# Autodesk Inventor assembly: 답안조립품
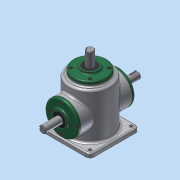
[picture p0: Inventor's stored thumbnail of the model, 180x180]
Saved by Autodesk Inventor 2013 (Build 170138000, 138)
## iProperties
Created: 2015-10
Part Number: 답안조립품
Document SubType Name: Assembly
Designer: dgall
Author: dgall
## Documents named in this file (14)
- C:\Users\dgall\Desktop\451007V1026\답안조립품.iam
- C:\Users\dgall\Desktop\451007V1026\본체.ipt
- C:\Users\dgall\Desktop\451007V1026\커버.ipt
- C:\Users\dgall\Desktop\451007V1026\베어링 6203.ipt
- C:\Users\dgall\Desktop\451007V1026\오일실.ipt
- C:\Users\dgall\Desktop\451007V1026\메인 축.ipt
- 메인 축.ipt
- C:\Users\dgall\Desktop\451007V1026\키 5x5.ipt
- C:\Users\dgall\Desktop\451007V1026\메인 베벨기어.ipt
- C:\Users\dgall\Desktop\451007V1026\서브 축.ipt
- 서브 축.ipt
- C:\Users\dgall\Desktop\451007V1026\키 4x4.ipt
- C:\Users\dgall\Desktop\451007V1026\서브 베벨기어.ipt
- C:\Users\dgall\Desktop\451007V1026\M4.ipt
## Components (12 placed, 1 different names)
1. M4:3
2. M4:4
3. M4:5
4. M4:6
5. M4:2
6. M4:7
7. M4:8
8. M4:9
9. M4:1
10. M4:10
11. M4:11
12. M4:12
